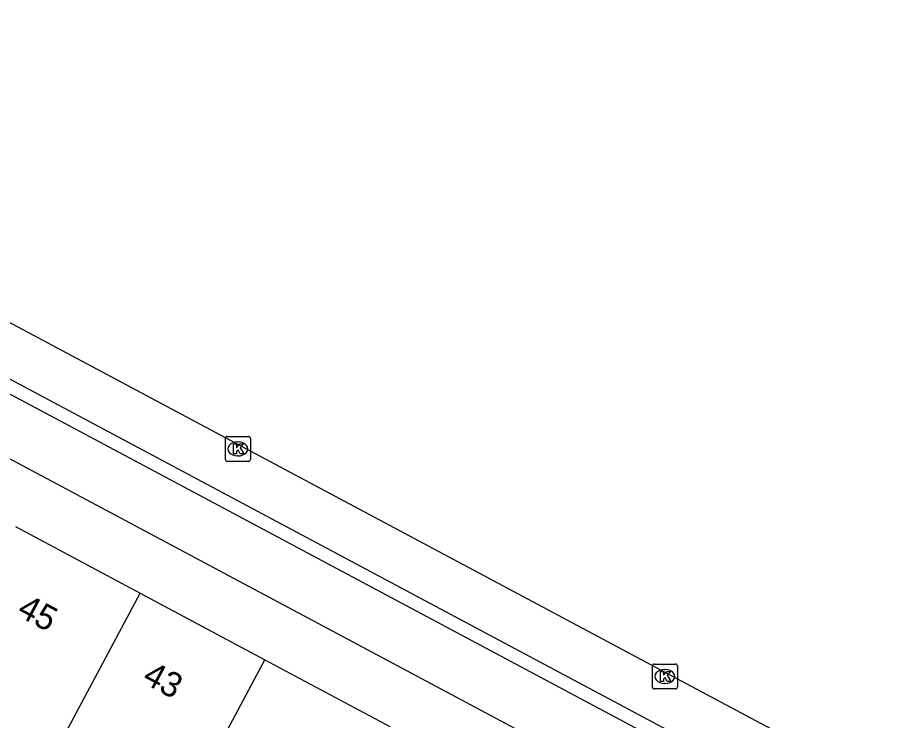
# Model space of a CAD drawing. Extents: x 159265 to 160143, y 383413 to 384319.
# Drawn here: x 159835.14 to 159869.94, y 383951.41 to 383979.65 of the extents above; entities that cross this region are included whole.
import ezdxf

# ---------------------------------------------------------------- set-up
doc = ezdxf.new("R2010")
doc.units = 0
for name, color, linetype in [('IMGEO_Fietspad_gesloten', 7, 'Continuous'), ('IMGEO_Kolk', 7, 'Continuous'), ('IMGEO_Pand', 7, 'Continuous'), ('IMGEO_Pand_nummerreeks', 7, 'Continuous'), ('IMGEO_Parkeervlak_open', 7, 'Continuous'), ('IMGEO_Rijbaan_lokaal_gesloten', 7, 'Continuous')]:
    doc.layers.add(name, color=color, linetype=linetype)

msp = doc.modelspace()

# ---------------------------------------------------------------- linework, layer by layer
at = {"layer": 'IMGEO_Fietspad_gesloten'}
for points in [[(159878.488, 383938.609), (159818.103, 383970.845), (159815.384, 383972.277), (159811.759, 383973.873), (159806.209, 383976.854), (159802.382, 383978.898)], [(159807.769, 383978.315), (159811.755, 383976.132), (159812.762, 383975.674), (159812.887, 383975.929), (159817.239, 383973.81), (159821.924, 383971.407), (159879.571, 383940.642)]]:
    msp.add_lwpolyline(points, dxfattribs=at)
at = {"layer": 'IMGEO_Kolk'}
for p, q in [((159843.487, 383961.894), (159843.487, 383962.746)), ((159843.562, 383962.82), (159844.414, 383962.82)), ((159843.975, 383962.6), (159844, 383962.6)), ((159844.488, 383962.746), (159844.488, 383961.894)), ((159844.414, 383961.82), (159843.562, 383961.82)), ((159843.998, 383962.04), (159843.973, 383962.04)), ((159860.623, 383952.757), (159860.623, 383953.609)), ((159860.698, 383953.683), (159861.55, 383953.683)), ((159861.111, 383953.463), (159861.136, 383953.463)), ((159861.624, 383953.609), (159861.624, 383952.757)), ((159861.134, 383952.903), (159861.109, 383952.903)), ((159861.55, 383952.683), (159860.698, 383952.683))]:
    msp.add_line(p, q, dxfattribs=at)
for points in [[(159843.487, 383961.894), (159843.487, 383962.746)], [(159843.562, 383962.82), (159844.414, 383962.82)], [(159843.808, 383962.52), (159843.931, 383962.52), (159843.931, 383962.369), (159844.061, 383962.52), (159844.225, 383962.52), (159844.079, 383962.369), (159844.232, 383962.12), (159844.08, 383962.12), (159843.995, 383962.284), (159843.931, 383962.217), (159843.931, 383962.12), (159843.808, 383962.12), (159843.808, 383962.52)], [(159844.488, 383962.746), (159844.488, 383961.894)], [(159844.414, 383961.82), (159843.562, 383961.82)], [(159860.623, 383952.757), (159860.623, 383953.609)], [(159860.698, 383953.683), (159861.55, 383953.683)], [(159861.624, 383953.609), (159861.624, 383952.757)], [(159860.944, 383953.383), (159861.067, 383953.383), (159861.067, 383953.232), (159861.197, 383953.383), (159861.361, 383953.383), (159861.215, 383953.232), (159861.368, 383952.983), (159861.216, 383952.983), (159861.131, 383953.147), (159861.067, 383953.08), (159861.067, 383952.983), (159860.944, 383952.983), (159860.944, 383953.383)], [(159861.55, 383952.683), (159860.698, 383952.683)]]:
    msp.add_lwpolyline(points, dxfattribs=at)
for centre, start, end in [((159843.564, 383962.744), 91.552, 178.448), ((159843.564, 383962.744), 91.552, 178.448), ((159844.412, 383962.744), 1.552, 88.448), ((159844.412, 383962.744), 1.552, 88.448), ((159843.564, 383961.896), 181.552, 268.448), ((159843.564, 383961.896), 181.552, 268.448), ((159844.412, 383961.896), 271.552, 358.448), ((159844.412, 383961.896), 271.552, 358.448), ((159860.7, 383953.607), 91.552, 178.448), ((159860.7, 383953.607), 91.552, 178.448), ((159861.548, 383953.607), 1.552, 88.448), ((159861.548, 383953.607), 1.552, 88.448), ((159860.7, 383952.759), 181.552, 268.448), ((159860.7, 383952.759), 181.552, 268.448), ((159861.548, 383952.759), 271.552, 358.448), ((159861.548, 383952.759), 271.552, 358.448)]:
    msp.add_arc(centre, 0.0765, start, end, dxfattribs=at)
for centre, major_axis, ratio, start_param, end_param in [((159843.974, 383962.32), (-0.387, 0.002), 0.722429, 4.712389, 7.853982), ((159843.999, 383962.32), (-0.39, 0.002), 0.717154, 1.570796, 4.712389), ((159861.11, 383953.183), (-0.387, 0.002), 0.722429, 4.712389, 7.853982), ((159861.135, 383953.183), (-0.39, 0.002), 0.717154, 1.570796, 4.712389)]:
    msp.add_ellipse(centre, major_axis=major_axis, ratio=ratio, start_param=start_param, end_param=end_param, dxfattribs=at)
at = {"layer": 'IMGEO_Pand'}
for points in [[(159835.066, 383959.206), (159840.07, 383956.528)], [(159836.546, 383949.927), (159840.07, 383956.528)], [(159840.07, 383956.528), (159845.075, 383953.849)], [(159838.786, 383942.066), (159838.844, 383942.177), (159845.075, 383953.849)], [(159845.075, 383953.849), (159850.08, 383951.17)]]:
    msp.add_lwpolyline(points, dxfattribs=at)
at = {"layer": 'IMGEO_Parkeervlak_open'}
msp.add_lwpolyline([(159885.523, 383938.052), (159822.09, 383971.919), (159813.13, 383976.392)], dxfattribs=at)
at = {"layer": 'IMGEO_Rijbaan_lokaal_gesloten'}
msp.add_lwpolyline([(159810.574, 383979.653), (159814.9, 383977.723), (159818.616, 383975.911), (159827.568, 383971.273), (159889.226, 383938.344)], dxfattribs=at)

# ---------------------------------------------------------------- texts
at = {"layer": 'IMGEO_Pand_nummerreeks'}
for s, p in [('45', (159835.076, 383955.651)), ('43', (159840.104, 383952.959))]:
    msp.add_text(s, height=1, rotation=331.8334, dxfattribs=at).set_placement(p)

doc.saveas('drawing.dxf')
